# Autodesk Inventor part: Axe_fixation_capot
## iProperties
Created: 2011-01
Part Number: Axe_fixation_capot
Document SubType Name: Modeling
Designer: eric
Density: 1 g/cm^3
Mass: 1.12112 g
Surface Area: 11.1546 cm^2
Volume: 1.12112 cm^3
Author: eric
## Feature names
1. Base1
